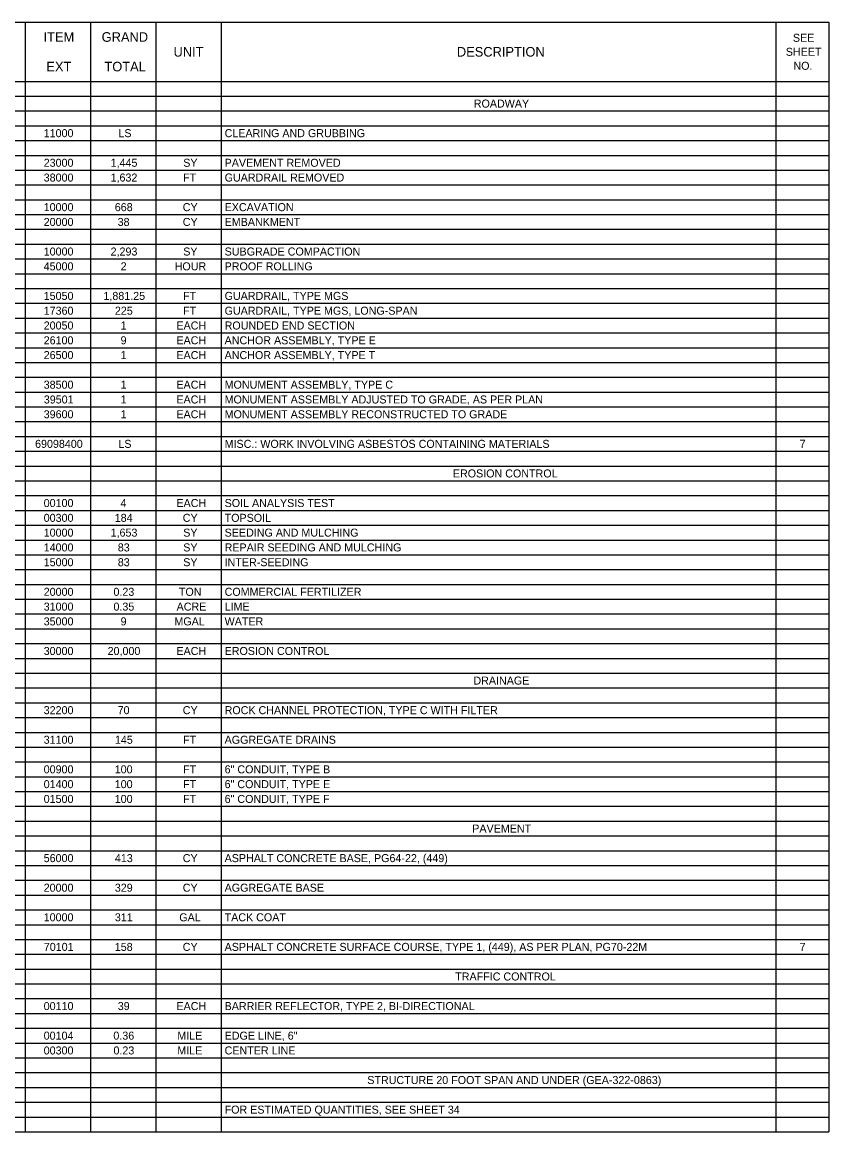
# Model space of a CAD drawing. Extents: x -31.7 to 37.3, y 0 to 22.
# Drawn here: x -16.46 to -1.2, y 0.32 to 21.32 of the extents above; entities that cross this region are included whole.
import ezdxf

# ---------------------------------------------------------------- set-up
doc = ezdxf.new("R2010")
doc.units = 0
doc.layers.add('Default', color=7, linetype='Continuous')

msp = doc.modelspace()

# ---------------------------------------------------------------- linework, layer by layer
at = {"layer": 'Default'}
for p, q in [((-31.705, 21.321), (-1.202, 21.321)), ((-16.404, 21.321), (-16.404, 0.321)), ((-15.169, 21.321), (-15.169, 0.321)), ((-13.933, 21.321), (-13.933, 0.321)), ((-12.698, 21.321), (-12.698, 0.321)), ((-2.206, 21.321), (-2.206, 0.321)), ((-1.202, 21.321), (-1.202, 0.321)), ((-31.705, 20.201), (-1.202, 20.201)), ((-31.705, 19.921), (-1.202, 19.921)), ((-31.705, 19.641), (-1.202, 19.641)), ((-31.705, 19.361), (-1.202, 19.361)), ((-31.705, 19.081), (-1.202, 19.081)), ((-31.705, 18.801), (-1.202, 18.801)), ((-31.705, 18.521), (-1.202, 18.521)), ((-31.705, 18.241), (-1.202, 18.241)), ((-31.705, 17.961), (-1.202, 17.961)), ((-31.705, 17.681), (-1.202, 17.681)), ((-31.705, 17.401), (-1.202, 17.401)), ((-31.705, 17.121), (-1.202, 17.121)), ((-31.705, 16.841), (-1.202, 16.841)), ((-31.705, 16.561), (-1.202, 16.561)), ((-31.705, 16.281), (-1.202, 16.281)), ((-31.705, 16.001), (-1.202, 16.001)), ((-31.705, 15.721), (-1.202, 15.721)), ((-31.705, 15.441), (-1.202, 15.441)), ((-31.705, 15.161), (-1.202, 15.161)), ((-31.705, 14.881), (-1.202, 14.881)), ((-31.705, 14.601), (-1.202, 14.601)), ((-31.705, 14.321), (-1.202, 14.321)), ((-31.705, 14.041), (-1.202, 14.041)), ((-31.705, 13.761), (-1.202, 13.761)), ((-31.705, 13.481), (-1.202, 13.481)), ((-31.705, 13.201), (-1.202, 13.201)), ((-31.705, 12.921), (-1.202, 12.921)), ((-31.705, 12.641), (-1.202, 12.641)), ((-31.705, 12.361), (-1.202, 12.361)), ((-31.705, 12.081), (-1.202, 12.081)), ((-31.705, 11.801), (-1.202, 11.801)), ((-31.705, 11.521), (-1.202, 11.521)), ((-31.705, 11.241), (-1.202, 11.241)), ((-31.705, 10.961), (-1.202, 10.961)), ((-31.705, 10.681), (-1.202, 10.681)), ((-31.705, 10.401), (-1.202, 10.401)), ((-31.705, 10.121), (-1.202, 10.121)), ((-31.705, 9.841), (-1.202, 9.841)), ((-31.705, 9.561), (-1.202, 9.561)), ((-31.705, 9.281), (-1.202, 9.281)), ((-31.705, 9.001), (-1.202, 9.001)), ((-31.705, 8.721), (-1.202, 8.721)), ((-31.705, 8.441), (-1.202, 8.441)), ((-31.705, 8.161), (-1.202, 8.161)), ((-31.705, 7.881), (-1.202, 7.881)), ((-31.705, 7.601), (-1.202, 7.601)), ((-31.705, 7.321), (-1.202, 7.321)), ((-31.705, 7.041), (-1.202, 7.041)), ((-31.705, 6.761), (-1.202, 6.761)), ((-31.705, 6.481), (-1.202, 6.481)), ((-31.705, 6.201), (-1.202, 6.201)), ((-31.705, 5.921), (-1.202, 5.921)), ((-31.705, 5.641), (-1.202, 5.641)), ((-31.705, 5.361), (-1.202, 5.361)), ((-31.705, 5.081), (-1.202, 5.081)), ((-31.705, 4.801), (-1.202, 4.801)), ((-31.705, 4.521), (-1.202, 4.521)), ((-31.705, 4.241), (-1.202, 4.241)), ((-31.705, 3.961), (-1.202, 3.961)), ((-31.705, 3.681), (-1.202, 3.681)), ((-31.705, 3.401), (-1.202, 3.401)), ((-31.705, 3.121), (-1.202, 3.121)), ((-31.705, 2.841), (-1.202, 2.841)), ((-31.705, 2.561), (-1.202, 2.561)), ((-31.705, 2.281), (-1.202, 2.281)), ((-31.705, 2.001), (-1.202, 2.001)), ((-31.705, 1.721), (-1.202, 1.721)), ((-31.705, 1.441), (-1.202, 1.441)), ((-31.705, 1.161), (-1.202, 1.161)), ((-31.705, 0.881), (-1.202, 0.881)), ((-31.705, 0.601), (-1.202, 0.601)), ((-31.705, 0.321), (-1.202, 0.321))]:
    msp.add_line(p, q, dxfattribs=at)

# ---------------------------------------------------------------- texts
for s, height, p in [('ITEM', 0.1818, (-16.058, 20.95)), ('GRAND', 0.1818, (-14.958, 20.95)), ('SEE ', 0.1515, (-1.881, 20.95)), ('UNIT', 0.1818, (-13.599, 20.67)), ('DESCRIPTION', 0.18184, (-8.238, 20.67)), ('SHEET ', 0.1515, (-2.015, 20.685)), ('EXT', 0.1818, (-16.004, 20.39)), ('TOTAL', 0.1818, (-14.906, 20.39)), ('NO.', 0.1515, (-1.871, 20.42)), ('ROADWAY', 0.1515, (-7.918, 19.705)), ('11000', 0.1515, (-16.055, 19.145)), ('LS', 0.1515, (-14.642, 19.145)), ('CLEARING AND GRUBBING', 0.15153, (-12.632, 19.145)), ('23000', 0.1515, (-16.055, 18.585)), ('1,445', 0.1515, (-14.789, 18.585)), ('SY', 0.1515, (-13.415, 18.585)), ('PAVEMENT REMOVED', 0.15153, (-12.632, 18.585)), ('38000', 0.1515, (-16.055, 18.305)), ('1,632', 0.1515, (-14.79, 18.305)), ('FT', 0.1515, (-13.417, 18.305)), ('GUARDRAIL REMOVED', 0.15153, (-12.632, 18.305)), ('10000', 0.1515, (-16.055, 17.745)), ('668', 0.1515, (-14.71, 17.745)), ('CY', 0.1515, (-13.424, 17.745)), ('EXCAVATION', 0.1515, (-12.632, 17.745)), ('20000', 0.1515, (-16.055, 17.465)), ('38', 0.1515, (-14.656, 17.465)), ('CY', 0.1515, (-13.424, 17.465)), ('EMBANKMENT', 0.1515, (-12.632, 17.465)), ('10000', 0.1515, (-16.055, 16.905)), ('2,293', 0.1515, (-14.789, 16.905)), ('SY', 0.1515, (-13.415, 16.905)), ('SUBGRADE COMPACTION', 0.15153, (-12.632, 16.905)), ('45000', 0.1515, (-16.055, 16.625)), ('2', 0.152, (-14.6, 16.625)), ('HOUR', 0.1515, (-13.577, 16.625)), ('PROOF ROLLING', 0.15153, (-12.632, 16.625)), ('15050', 0.1515, (-16.055, 16.065)), ('1,881.25', 0.1515, (-14.925, 16.065)), ('FT', 0.1515, (-13.417, 16.065)), ('GUARDRAIL, TYPE MGS', 0.15153, (-12.632, 16.065)), ('17360', 0.1515, (-16.055, 15.785)), ('225', 0.1515, (-14.708, 15.785)), ('FT', 0.1515, (-13.417, 15.785)), ('GUARDRAIL, TYPE MGS, LONG-SPAN', 0.15153, (-12.632, 15.785)), ('20050', 0.1515, (-16.055, 15.505)), ('1', 0.152, (-14.6, 15.505)), ('EACH', 0.1515, (-13.544, 15.505)), ('ROUNDED END SECTION', 0.15153, (-12.632, 15.505)), ('26100', 0.1515, (-16.055, 15.225)), ('9', 0.152, (-14.6, 15.225)), ('EACH', 0.1515, (-13.544, 15.225)), ('ANCHOR ASSEMBLY, TYPE E', 0.15153, (-12.632, 15.225)), ('26500', 0.1515, (-16.055, 14.945)), ('1', 0.152, (-14.6, 14.945)), ('EACH', 0.1515, (-13.544, 14.945)), ('ANCHOR ASSEMBLY, TYPE T', 0.15153, (-12.632, 14.945)), ('38500', 0.1515, (-16.055, 14.385)), ('1', 0.152, (-14.6, 14.385)), ('EACH', 0.1515, (-13.544, 14.385)), ('MONUMENT ASSEMBLY, TYPE C', 0.15153, (-12.632, 14.385)), ('39501', 0.1515, (-16.053, 14.105)), ('1', 0.152, (-14.6, 14.105)), ('EACH', 0.1515, (-13.544, 14.105)), ('MONUMENT ASSEMBLY ADJUSTED TO GRADE, AS PER PLAN', 0.15153, (-12.632, 14.105)), ('39600', 0.1515, (-16.055, 13.825)), ('1', 0.152, (-14.6, 13.825)), ('EACH', 0.1515, (-13.544, 13.825)), ('MONUMENT ASSEMBLY RECONSTRUCTED TO GRADE', 0.15153, (-12.632, 13.825)), ('69098400', 0.1515, (-16.218, 13.265)), ('LS', 0.1515, (-14.642, 13.265)), ('MISC.: WORK INVOLVING ASBESTOS CONTAINING MATERIALS', 0.15153, (-12.632, 13.265)), ('7', 0.152, (-1.754, 13.265)), ('EROSION CONTROL', 0.15153, (-8.314, 12.705)), ('00100', 0.1515, (-16.055, 12.145)), ('4', 0.152, (-14.602, 12.145)), ('EACH', 0.1515, (-13.544, 12.145)), ('SOIL ANALYSIS TEST', 0.15153, (-12.632, 12.145)), ('00300', 0.1515, (-16.055, 11.865)), ('184', 0.1515, (-14.711, 11.865)), ('CY', 0.1515, (-13.424, 11.865)), ('TOPSOIL', 0.1515, (-12.632, 11.865)), ('10000', 0.1515, (-16.055, 11.585)), ('1,653', 0.1515, (-14.789, 11.585)), ('SY', 0.1515, (-13.415, 11.585)), ('SEEDING AND MULCHING', 0.15153, (-12.632, 11.585)), ('14000', 0.1515, (-16.055, 11.305)), ('83', 0.1515, (-14.653, 11.305)), ('SY', 0.1515, (-13.415, 11.305)), ('REPAIR SEEDING AND MULCHING', 0.15153, (-12.632, 11.305)), ('15000', 0.1515, (-16.055, 11.025)), ('83', 0.1515, (-14.653, 11.025)), ('SY', 0.1515, (-13.415, 11.025)), ('INTER-SEEDING', 0.15153, (-12.632, 11.025)), ('20000', 0.1515, (-16.055, 10.465)), ('0.23', 0.1515, (-14.735, 10.465)), ('TON', 0.1515, (-13.497, 10.465)), ('COMMERCIAL FERTILIZER', 0.15153, (-12.632, 10.465)), ('31000', 0.1515, (-16.055, 10.185)), ('0.35', 0.1515, (-14.735, 10.185)), ('ACRE', 0.1515, (-13.54, 10.185)), ('LIME', 0.1515, (-12.632, 10.185)), ('35000', 0.1515, (-16.055, 9.905)), ('9', 0.152, (-14.6, 9.905)), ('MGAL', 0.1515, (-13.582, 9.905)), ('WATER', 0.1515, (-12.632, 9.905)), ('30000', 0.1515, (-16.055, 9.345)), ('20,000', 0.1515, (-14.846, 9.345)), ('EACH', 0.1515, (-13.544, 9.345)), ('EROSION CONTROL', 0.15153, (-12.632, 9.345)), ('DRAINAGE', 0.1515, (-7.925, 8.785)), ('32200', 0.1515, (-16.055, 8.225)), ('70', 0.1515, (-14.656, 8.225)), ('CY', 0.1515, (-13.424, 8.225)), ('ROCK CHANNEL PROTECTION, TYPE C WITH FILTER', 0.15153, (-12.632, 8.225)), ('31100', 0.1515, (-16.055, 7.665)), ('145', 0.1515, (-14.708, 7.665)), ('FT', 0.1515, (-13.417, 7.665)), ('AGGREGATE DRAINS', 0.15153, (-12.632, 7.665)), ('00900', 0.1515, (-16.055, 7.105)), ('100', 0.1515, (-14.711, 7.105)), ('FT', 0.1515, (-13.417, 7.105)), ('6" CONDUIT, TYPE B', 0.15153, (-12.632, 7.105)), ('01400', 0.1515, (-16.055, 6.825)), ('100', 0.1515, (-14.711, 6.825)), ('FT', 0.1515, (-13.417, 6.825)), ('6" CONDUIT, TYPE E', 0.15153, (-12.632, 6.825)), ('01500', 0.1515, (-16.055, 6.545)), ('100', 0.1515, (-14.711, 6.545)), ('FT', 0.1515, (-13.417, 6.545)), ('6" CONDUIT, TYPE F', 0.15153, (-12.632, 6.545)), ('PAVEMENT', 0.1515, (-7.947, 5.985)), ('56000', 0.1515, (-16.055, 5.425)), ('413', 0.1515, (-14.708, 5.425)), ('CY', 0.1515, (-13.424, 5.425)), ('ASPHALT CONCRETE BASE, PG64-22, (449)', 0.15153, (-12.632, 5.425)), ('20000', 0.1515, (-16.055, 4.865)), ('329', 0.1515, (-14.709, 4.865)), ('CY', 0.1515, (-13.424, 4.865)), ('AGGREGATE BASE', 0.15153, (-12.632, 4.865)), ('10000', 0.1515, (-16.055, 4.305)), ('311', 0.1515, (-14.709, 4.305)), ('GAL', 0.1515, (-13.49, 4.305)), ('TACK COAT', 0.1515, (-12.632, 4.305)), ('70101', 0.1515, (-16.053, 3.745)), ('158', 0.1515, (-14.71, 3.745)), ('CY', 0.1515, (-13.424, 3.745)), ('ASPHALT CONCRETE SURFACE COURSE, TYPE 1, (449), AS PER PLAN, PG70-22M', 0.15153, (-12.632, 3.745)), ('7', 0.152, (-1.754, 3.745)), ('TRAFFIC CONTROL', 0.15153, (-8.269, 3.185)), ('00110', 0.1515, (-16.055, 2.625)), ('39', 0.1515, (-14.654, 2.625)), ('EACH', 0.1515, (-13.544, 2.625)), ('BARRIER REFLECTOR, TYPE 2, BI-DIRECTIONAL', 0.15153, (-12.632, 2.625)), ('00104', 0.1515, (-16.055, 2.065)), ('0.36', 0.1515, (-14.737, 2.065)), ('MILE', 0.1515, (-13.527, 2.065)), ('EDGE LINE, 6"', 0.15153, (-12.632, 2.065)), ('00300', 0.1515, (-16.055, 1.785)), ('0.23', 0.1515, (-14.735, 1.785)), ('MILE', 0.1515, (-13.527, 1.785)), ('CENTER LINE', 0.15153, (-12.632, 1.785)), ('STRUCTURE 20 FOOT SPAN AND UNDER (GEA-322-0863)', 0.15153, (-9.933, 1.225)), ('FOR ESTIMATED QUANTITIES, SEE SHEET 34', 0.15153, (-12.632, 0.665))]:
    msp.add_text(s, height=height, dxfattribs=at).set_placement(p)

doc.saveas('drawing.dxf')
